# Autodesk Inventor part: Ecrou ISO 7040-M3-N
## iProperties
Created: 2011-01
Part Number: Ecrou ISO 7040-M3-N
Document SubType Name: Modeling
Designer: eric
Density: 1 g/cm^3
Mass: 0.0826944 g
Surface Area: 1.53081 cm^2
Volume: 0.0826944 cm^3
Author: eric
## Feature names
1. Base1
